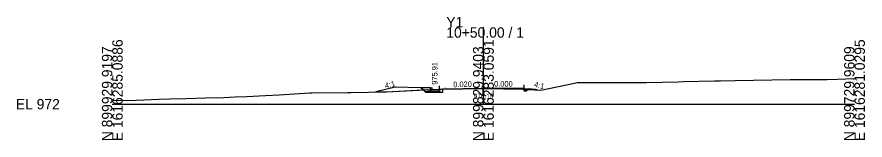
# Model space of a CAD drawing. Extents: x -26 to 203, y -10 to 2022.
# Drawn here: x -25.7 to 202.8, y 490.3 to 523.5 of the extents above; entities that cross this region are included whole.
import ezdxf

# ---------------------------------------------------------------- set-up
doc = ezdxf.new("R2010")
doc.units = 0
for name, color, linetype in [('Default', 7, 'Continuous'), ('Exist Cross Section Cell', 7, 'Continuous'), ('Exist XS Center Line Elevation Label', 7, 'Continuous'), ('Exist XS Ground Line', 7, 'Continuous'), ('Prop XS Ditch Slope Text', 7, 'Continuous'), ('Prop XS Dump Level', 7, 'Continuous'), ('Prop XS Earthwork Shape', 7, 'Continuous'), ('Prop XS EOT Tick Mark', 7, 'Continuous'), ('Prop XS Finish Grade', 7, 'Continuous'), ('Prop XS Finish Grade CurbGutter', 7, 'Continuous'), ('Prop XS Finish Grade Earthwork', 7, 'Continuous'), ('Prop XS Finish Grade Pavement', 7, 'Continuous'), ('Prop XS Pvmt Edge Slope', 7, 'Continuous'), ('Prop XS SE Text', 7, 'Continuous'), ('Prop XS Subgrade CurbGutter', 7, 'Continuous'), ('Prop XS Subgrade Earthwork', 7, 'Continuous')]:
    doc.layers.add(name, color=color, linetype=linetype)

msp = doc.modelspace()

# ---------------------------------------------------------------- linework, layer by layer
at = {"layer": 'Exist Cross Section Cell'}
for p, q in [((100, 500), (100, 520.74)), ((0, 500), (100, 500)), ((100, 500), (200, 500))]:
    msp.add_line(p, q, dxfattribs=at)
at = {"layer": 'Exist XS Ground Line'}
for p, q in [((115.51, 503.75), (124.54, 505.65)), ((124.54, 505.65), (125.31, 505.81)), ((125.31, 505.81), (141.81, 505.83)), ((141.81, 505.83), (143.89, 505.86)), ((143.89, 505.86), (152.49, 506.06)), ((152.49, 506.06), (153.89, 506.09)), ((153.89, 506.09), (162.29, 506.3)), ((162.29, 506.3), (163.89, 506.33)), ((163.89, 506.33), (167.85, 506.36)), ((167.85, 506.36), (182.62, 506.63)), ((182.62, 506.63), (187.44, 506.63)), ((187.44, 506.63), (191.92, 506.67)), ((191.92, 506.67), (192.67, 506.68)), ((192.67, 506.68), (195.35, 506.76)), ((195.35, 506.76), (200, 506.91)), ((44.98, 502.48), (53.25, 503.04)), ((53.25, 503.04), (53.86, 503.06)), ((53.86, 503.06), (63.46, 503.12)), ((63.46, 503.12), (63.87, 503.13)), ((63.87, 503.13), (64.26, 503.13)), ((64.26, 503.13), (73.87, 503.37)), ((73.87, 503.37), (87.99, 504.05)), ((87.99, 504.05), (88.99, 504.12)), ((88.99, 504.12), (98.62, 504.2)), ((98.62, 504.2), (99.51, 504.2)), ((99.51, 504.2), (100, 504.19)), ((100, 504.19), (110.71, 504.06)), ((110.71, 504.06), (112.11, 503.98)), ((112.11, 503.98), (112.74, 503.95)), ((112.74, 503.95), (115.51, 503.75)), ((0, 500.96), (6.41, 501.04)), ((6.41, 501.04), (12.53, 501.31)), ((12.53, 501.31), (15.41, 501.43)), ((15.41, 501.43), (19.78, 501.55)), ((19.78, 501.55), (25.13, 501.75)), ((25.13, 501.75), (30.07, 501.8)), ((30.07, 501.8), (33.08, 501.96)), ((33.08, 501.96), (36.21, 502.07)), ((36.21, 502.07), (41.29, 502.34)), ((41.29, 502.34), (44.98, 502.48))]:
    msp.add_line(p, q, dxfattribs=at)
at = {"layer": 'Prop XS Dump Level'}
for p, q in [((89, 504.01), (88.2, 503.99)), ((100, 504.23), (89, 504.01)), ((111, 504.23), (100, 504.23))]:
    msp.add_line(p, q, dxfattribs=at)
at = {"layer": 'Prop XS Earthwork Shape'}
for points in [[(83.74, 503.85), (83.14, 504.45), (76.2, 504.6), (71, 503.3), (73.87, 503.37)], [(83.74, 503.85), (85.7, 503.94), (85.7, 503.4), (84.7, 503.39), (84.45, 503.14)], [(86.29, 503.97), (87.99, 504.05), (88.99, 504.12), (89, 503.17), (88.2, 503.16), (84.45, 503.14), (84.7, 503.39), (85.7, 503.4), (88.2, 503.41), (88.2, 503.99), (86.45, 503.91), (86.32, 503.94)], [(85.7, 503.94), (86.29, 503.97), (86.32, 503.94), (86.45, 503.91), (88.2, 503.99), (88.2, 503.41), (85.7, 503.4)], [(111, 504.05), (111.19, 504.03), (111.6, 503.63), (111, 503.64)], [(111.19, 504.03), (111.96, 503.99), (111.6, 503.63)], [(111.96, 503.99), (112.11, 503.98), (112.74, 503.95), (114.71, 503.81), (114, 503.99), (112.11, 504.14)]]:
    msp.add_lwpolyline(points, close=True, dxfattribs=at)
at = {"layer": 'Prop XS EOT Tick Mark'}
for p, q in [((111, 504.23), (111, 505.23)), ((88.2, 503.99), (88.2, 504.99))]:
    msp.add_line(p, q, dxfattribs=at)
at = {"layer": 'Prop XS Finish Grade'}
for p, q in [((85.7, 504.4), (83.14, 504.45)), ((111, 504.23), (112.11, 504.14))]:
    msp.add_line(p, q, dxfattribs=at)
at = {"layer": 'Prop XS Finish Grade CurbGutter'}
for p, q in [((85.7, 504.4), (85.95, 504.4)), ((85.95, 504.4), (86.07, 504.37)), ((86.17, 504.28), (86.07, 504.37)), ((86.23, 504.03), (86.17, 504.28)), ((86.32, 503.94), (86.23, 504.03)), ((86.45, 503.91), (86.32, 503.94)), ((88.2, 503.99), (86.45, 503.91))]:
    msp.add_line(p, q, dxfattribs=at)
at = {"layer": 'Prop XS Finish Grade Earthwork'}
for p, q in [((76.2, 504.6), (71, 503.3)), ((83.14, 504.45), (76.2, 504.6)), ((112.11, 504.14), (114, 503.99)), ((114, 503.99), (114.71, 503.81))]:
    msp.add_line(p, q, dxfattribs=at)
at = {"layer": 'Prop XS Finish Grade Pavement'}
for p, q in [((88.2, 503.99), (89, 504.01)), ((89, 504.01), (100, 504.23)), ((100, 504.23), (111, 504.23))]:
    msp.add_line(p, q, dxfattribs=at)
at = {"layer": 'Prop XS Pvmt Edge Slope'}
for p, q in [((84.7, 503.39), (84.45, 503.14)), ((85.7, 503.4), (84.7, 503.39)), ((111, 504.23), (111.6, 503.63))]:
    msp.add_line(p, q, dxfattribs=at)
at = {"layer": 'Prop XS Subgrade CurbGutter'}
for p, q in [((85.7, 503.4), (85.7, 504.4)), ((88.2, 503.41), (85.7, 503.4)), ((88.2, 503.99), (88.2, 503.41))]:
    msp.add_line(p, q, dxfattribs=at)
at = {"layer": 'Prop XS Subgrade Earthwork'}
for p, q in [((84.45, 503.14), (83.14, 504.45)), ((88.2, 503.16), (84.45, 503.14)), ((89, 503.17), (88.2, 503.16)), ((88.99, 504.12), (89, 503.17)), ((111, 503.64), (111, 504.22)), ((111, 503.64), (111, 503.64)), ((111, 503.64), (111.6, 503.63)), ((111.6, 503.63), (112.11, 504.14))]:
    msp.add_line(p, q, dxfattribs=at)

# ---------------------------------------------------------------- texts
at = {"layer": 'Default'}
msp.add_text('975.91', height=1.5, rotation=90, dxfattribs=at).set_placement((87.63, 505.25))
at = {"layer": 'Exist Cross Section Cell'}
for s, p in [('Y1', (90, 520.74)), ('10+50.00 / 1', (90, 517.94)), ('EL 972', (-26, 498.6))]:
    msp.add_text(s, height=2.8, dxfattribs=at).set_placement(p)
for s, p in [('E 1616285.0886', (2.8, 490)), ('E 1616283.0591', (102.8, 490)), ('E 1616281.0295', (202.8, 490)), ('N 899929.9197', (0, 490)), ('N 899829.9403', (100, 490)), ('N 899729.9609', (200, 490))]:
    msp.add_text(s, height=2.8, rotation=90, dxfattribs=at).set_placement(p)
at = {"layer": 'Exist XS Center Line Elevation Label'}
msp.add_text('976.19', height=1.25, dxfattribs=at).set_placement((97.42, 501.56))
at = {"layer": 'Prop XS Ditch Slope Text'}
for rotation, p in [(14.0362, (73.63, 504.21)), (345.9638, (113.54, 504.69))]:
    msp.add_text('4:1', height=1.5, rotation=rotation, dxfattribs=at).set_placement(p)
at = {"layer": 'Prop XS Dump Level'}
for p in [(89.26, 504.19), (111, 503.92)]:
    msp.add_text('Eop', height=0.3, dxfattribs=at).set_placement(p)
at = {"layer": 'Prop XS SE Text'}
for s, rotation, p in [('0.020', 1.1458, (91.88, 504.56)), ('0.000', 359.9916, (102.88, 504.73))]:
    msp.add_text(s, height=1.5, rotation=rotation, dxfattribs=at).set_placement(p)

doc.saveas('drawing.dxf')
